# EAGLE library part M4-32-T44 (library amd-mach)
AMD MACH SERIES
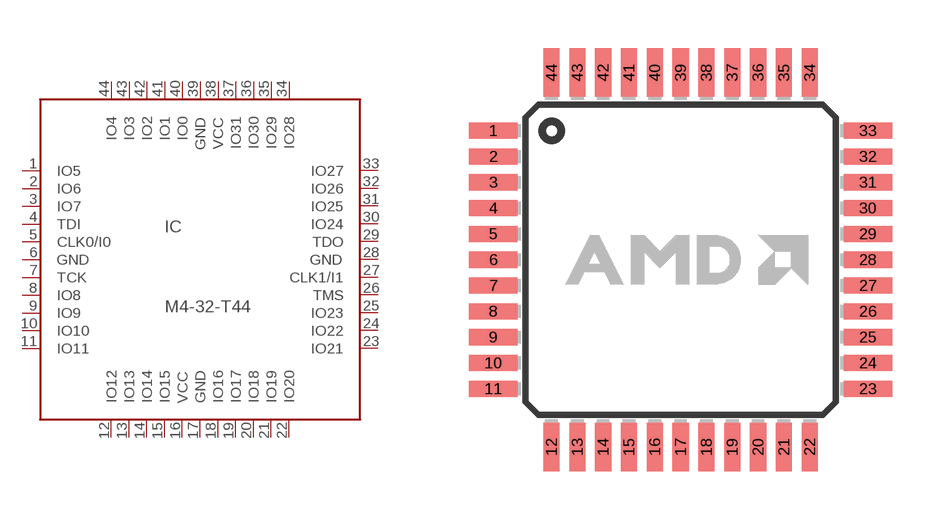
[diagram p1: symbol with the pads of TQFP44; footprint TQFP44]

Designator prefix IC

## M4-32-T44 (OC_FARNELL: unknown; OC_NEWARK: unknown)  [TQFP44]
1  IO5
2  IO6
3  IO7
4  TDI  in
5  CLK0/I0  in
6  GND  pwr
7  TCK  in
8  IO8
9  IO9
10  IO10
11  IO11
12  IO12
13  IO13
14  IO14
15  IO15
16  VCC  pwr
17  GND  pwr
18  IO16
19  IO17
20  IO18
21  IO19
22  IO20
23  IO21
24  IO22
25  IO23
26  TMS  in
27  CLK1/I1  in
28  GND  pwr
29  TDO  out
30  IO24
31  IO25
32  IO26
33  IO27
34  IO28
35  IO29
36  IO30
37  IO31
38  VCC  pwr
39  GND  pwr
40  IO0
41  IO1
42  IO2
43  IO3
44  IO4

## Footprint TQFP44 (pad centres in mm)
THIN QUAD FLAT PACK
smd 1.5 x 0.5: 1 -5.8,4; 2 -5.8,3.2; 3 -5.8,2.4; 4 -5.8,1.6; 5 -5.8,0.8; 6 -5.8,0; 7 -5.8,-0.8; 8 -5.8,-1.6; 9 -5.8,-2.4; 10 -5.8,-3.2; 11 -5.8,-4; 23 5.8,-4; 24 5.8,-3.2; 25 5.8,-2.4; 26 5.8,-1.6; 27 5.8,-0.8; 28 5.8,0; 29 5.8,0.8; 30 5.8,1.6; 31 5.8,2.4; 32 5.8,3.2; 33 5.8,4
smd 0.5 x 1.5: 12 -4,-5.8; 13 -3.2,-5.8; 14 -2.4,-5.8; 15 -1.6,-5.8; 16 -0.8,-5.8; 17 0,-5.8; 18 0.8,-5.8; 19 1.6,-5.8; 20 2.4,-5.8; 21 3.2,-5.8; 22 4,-5.8; 34 4,5.8; 35 3.2,5.8; 36 2.4,5.8; 37 1.6,5.8; 38 0.8,5.8; 39 0,5.8; 40 -0.8,5.8; 41 -1.6,5.8; 42 -2.4,5.8; 43 -3.2,5.8; 44 -4,5.8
